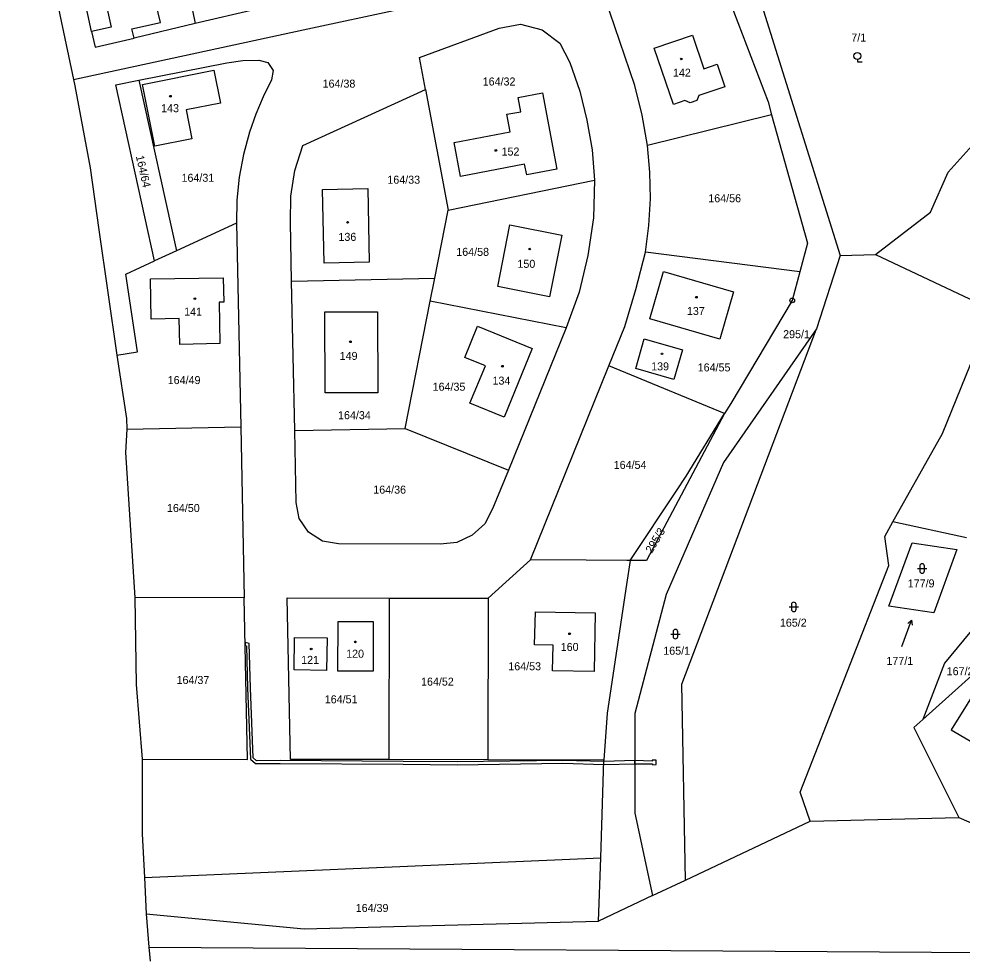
# Model space of a CAD drawing. Extents: x -779723 to -777378, y -1011169 to -1009297.
# Drawn here: x -779423.2 to -779222.9, y -1010475.7 to -1010276.4 of the extents above; entities that cross this region are included whole.
import ezdxf

# ---------------------------------------------------------------- set-up
doc = ezdxf.new("R2010")
doc.units = 0
for name, color, linetype in [('Hranice parcel', 7, 'Continuous'), ('Parcelní čísla', 7, 'Continuous'), ('Poz předměty', 7, 'Continuous'), ('Věcná břemena k části', 7, 'Continuous'), ('Značky bodu BP', 7, 'Continuous'), ('Značky budov', 7, 'Continuous'), ('Značky kultur', 7, 'Continuous')]:
    doc.layers.add(name, color=color, linetype=linetype)

msp = doc.modelspace()

# ---------------------------------------------------------------- linework, layer by layer
at = {"layer": 'Hranice parcel'}
for p, q in [((-779423.17, -1010234.28), (-779411.57, -1010289.24)), ((-779390.67, -1010252.85), (-779385.75, -1010277.38)), ((-779407.72, -1010279.08), (-779412.45, -1010257.73)), ((-779292.43, -1010290.53), (-779300.99, -1010265.39)), ((-779372.96, -1010274.36), (-779385.75, -1010277.38)), ((-779385.75, -1010277.38), (-779398.69, -1010280.44)), ((-779397.7, -1010289.41), (-779389.74, -1010325.58)), ((-779336.86, -1010291.37), (-779332.05, -1010316.98)), ((-779263.36, -1010296.74), (-779289.73, -1010303.24)), ((-779332.05, -1010316.98), (-779301, -1010310.57)), ((-779334.89, -1010331.42), (-779332.05, -1010316.98)), ((-779406.22, -1010321.12), (-779402.4, -1010347.73)), ((-779376.98, -1010319.73), (-779389.74, -1010325.58)), ((-779376.98, -1010319.73), (-779376.08, -1010362.91)), ((-779389.74, -1010325.58), (-779394.39, -1010327.71)), ((-779257.37, -1010330.02), (-779290.15, -1010325.87)), ((-779248.83, -1010326.61), (-779253.82, -1010342.15)), ((-779248.83, -1010326.61), (-779241.34, -1010326.4)), ((-779365.26, -1010332.05), (-779334.89, -1010331.42)), ((-779364.6, -1010363.75), (-779365.26, -1010332.05)), ((-779335.84, -1010336.25), (-779334.89, -1010331.42)), ((-779341.15, -1010363.28), (-779335.84, -1010336.25)), ((-779307.01, -1010341.91), (-779335.84, -1010336.25)), ((-779307.01, -1010341.91), (-779319.25, -1010372.13)), ((-779402.4, -1010347.73), (-779397.95, -1010347.05)), ((-779314.54, -1010391.18), (-779297.93, -1010350.03)), ((-779273.36, -1010360.11), (-779297.93, -1010350.03)), ((-779400.24, -1010363.41), (-779376.08, -1010362.91)), ((-779376.08, -1010362.91), (-779375.32, -1010399.25)), ((-779364.6, -1010363.75), (-779341.15, -1010363.28)), ((-779341.15, -1010363.28), (-779319.25, -1010372.13)), ((-779400.24, -1010363.41), (-779400.52, -1010368.39)), ((-779400.52, -1010368.39), (-779398.58, -1010399.19)), ((-779222.02, -1010386.49), (-779237.61, -1010383.13)), ((-779323.52, -1010399.33), (-779314.54, -1010391.18)), ((-779375.32, -1010399.25), (-779398.58, -1010399.19)), ((-779374.61, -1010433.5), (-779375.32, -1010399.25)), ((-779344.55, -1010433.56), (-779344.47, -1010399.29)), ((-779344.47, -1010399.29), (-779323.52, -1010399.33)), ((-779323.52, -1010399.33), (-779323.6, -1010433.61)), ((-779231.29, -1010425.07), (-779220.25, -1010415.13)), ((-779396.98, -1010433.44), (-779374.61, -1010433.5)), ((-779323.6, -1010433.61), (-779344.55, -1010433.56)), ((-779298.95, -1010433.67), (-779323.6, -1010433.61)), ((-779299.64, -1010454.37), (-779298.95, -1010433.67)), ((-779281.67, -1010459.12), (-779255.18, -1010446.63)), ((-779255.18, -1010446.63), (-779223.61, -1010445.86)), ((-779396.51, -1010458.6), (-779299.64, -1010454.37)), ((-779300.09, -1010467.81), (-779299.64, -1010454.37)), ((-779396.51, -1010458.6), (-779396.12, -1010466.31)), ((-779288.66, -1010462.42), (-779281.67, -1010459.12)), ((-779288.66, -1010462.42), (-779300.09, -1010467.81))]:
    msp.add_line(p, q, dxfattribs=at)
for points in [[(-779267.64, -1010229.61), (-779274.18, -1010236), (-779275.45, -1010241.64), (-779248.83, -1010326.61)], [(-779276.95, -1010260.2), (-779264.13, -1010293.98), (-779263.36, -1010296.74)], [(-779398.69, -1010280.44), (-779399.16, -1010278.51), (-779393.09, -1010277.12), (-779396.07, -1010264.73), (-779406.08, -1010266.98), (-779403.57, -1010278.12), (-779407.72, -1010279.08)], [(-779411.57, -1010289.24), (-779362.78, -1010278.71), (-779320.52, -1010269.6)], [(-779407.72, -1010279.08), (-779406.99, -1010282.4), (-779398.69, -1010280.44)], [(-779336.86, -1010291.37), (-779338.14, -1010284.55), (-779321.24, -1010278.36), (-779316.65, -1010277.51), (-779312.1, -1010278.67), (-779308.36, -1010281.51), (-779306.17, -1010285.63), (-779304.1, -1010291.71), (-779302.56, -1010297.89), (-779301.46, -1010304.17), (-779301, -1010310.57)], [(-779280.65, -1010294.17), (-779281.79, -1010293.68), (-779284.23, -1010294.51), (-779288.27, -1010282.58), (-779280.15, -1010279.85), (-779277.75, -1010286.96), (-779274.91, -1010286.01), (-779273.29, -1010290.79), (-779278.8, -1010292.6), (-779279.24, -1010293.68), (-779280.65, -1010294.17)], [(-779397.7, -1010289.41), (-779379.01, -1010285.72), (-779375.64, -1010285.2), (-779372.24, -1010285.16), (-779370.29, -1010285.62), (-779369.18, -1010287.35), (-779369.57, -1010289.31), (-779371.31, -1010292.92), (-779372.85, -1010296.61), (-779374.18, -1010300.38), (-779375.49, -1010305.12), (-779376.4, -1010309.95), (-779376.91, -1010314.83), (-779376.98, -1010319.73)], [(-779411.57, -1010289.24), (-779411.29, -1010290.56), (-779408.01, -1010308), (-779406.22, -1010321.12)], [(-779380.38, -1010294.23), (-779387.63, -1010295.67), (-779386.44, -1010301.84), (-779394.32, -1010303.41), (-779396.93, -1010290.27), (-779381.75, -1010287.29), (-779380.38, -1010294.23)], [(-779394.39, -1010327.71), (-779402.61, -1010290.38), (-779397.7, -1010289.41)], [(-779289.73, -1010303.24), (-779290.82, -1010296.83), (-779292.43, -1010290.53)], [(-779365.26, -1010332.05), (-779365.52, -1010319.51), (-779365.44, -1010313.99), (-779364.55, -1010308.53), (-779362.87, -1010303.27), (-779336.86, -1010291.37)], [(-779312.04, -1010292.07), (-779308.98, -1010308.25), (-779315.34, -1010309.48), (-779315.8, -1010307.17), (-779329.38, -1010309.79), (-779330.76, -1010302.6), (-779318.86, -1010300.34), (-779319.57, -1010296.61), (-779316.63, -1010296.07), (-779317.19, -1010293.07), (-779312.04, -1010292.07)], [(-779263.36, -1010296.74), (-779255.74, -1010323.95), (-779257.37, -1010330.02)], [(-779241.34, -1010326.4), (-779229.64, -1010317.38), (-779225.92, -1010308.91), (-779220.82, -1010303.25), (-779218.66, -1010301.14)], [(-779290.15, -1010325.87), (-779289.42, -1010320.24), (-779289.09, -1010314.57), (-779289.19, -1010308.89), (-779289.73, -1010303.24)], [(-779301, -1010310.57), (-779301.2, -1010318.61), (-779302.4, -1010326.55), (-779304.22, -1010334.38), (-779307.01, -1010341.91)], [(-779349.07, -1010312.38), (-779348.8, -1010328.01), (-779358.39, -1010328.18), (-779358.71, -1010312.55), (-779349.07, -1010312.38)], [(-779310.5, -1010335.33), (-779321.5, -1010333.19), (-779318.95, -1010320.1), (-779307.92, -1010322.25), (-779310.5, -1010335.33)], [(-779297.93, -1010350.03), (-779294.54, -1010341.64), (-779292.21, -1010333.83), (-779290.15, -1010325.87)], [(-779241.34, -1010326.4), (-779216.41, -1010338.1), (-779212.98, -1010339.7)], [(-779397.95, -1010347.05), (-779400.48, -1010330.51), (-779394.39, -1010327.71)], [(-779380.48, -1010345.29), (-779388.99, -1010345.45), (-779389.11, -1010339.96), (-779395.11, -1010340.07), (-779395.24, -1010331.56), (-779379.78, -1010331.29), (-779379.66, -1010336.48), (-779380.68, -1010336.5), (-779380.48, -1010345.29)], [(-779289.25, -1010340.01), (-779286.34, -1010329.98), (-779271.46, -1010334.31), (-779274.38, -1010344.34), (-779289.25, -1010340.01)], [(-779257.37, -1010330.02), (-779259, -1010336.11), (-779272.05, -1010357.97), (-779273.36, -1010360.11)], [(-779346.99, -1010355.72), (-779358.16, -1010355.75), (-779358.24, -1010338.57), (-779347.03, -1010338.54), (-779346.99, -1010355.72)], [(-779237.61, -1010383.13), (-779227.1, -1010364.33), (-779217.17, -1010339.95), (-779210.43, -1010343.11), (-779209.31, -1010341.42)], [(-779325.78, -1010341.59), (-779314.2, -1010346.31), (-779320.16, -1010360.9), (-779327.4, -1010357.94), (-779324.14, -1010349.97), (-779328.48, -1010348.2), (-779325.78, -1010341.59)], [(-779253.82, -1010342.15), (-779273.57, -1010370.48), (-779285.76, -1010398.5), (-779292.43, -1010423.76), (-779292.43, -1010444.9), (-779288.66, -1010462.42)], [(-779281.67, -1010459.12), (-779282.45, -1010417.52), (-779253.82, -1010342.15)], [(-779292.22, -1010350.54), (-779290.41, -1010344.29), (-779282.31, -1010346.63), (-779284.12, -1010352.88), (-779292.22, -1010350.54)], [(-779402.4, -1010347.73), (-779400.35, -1010361.15), (-779400.24, -1010363.41)], [(-779273.36, -1010360.11), (-779289.96, -1010391.32), (-779293.41, -1010391.29)], [(-779293.41, -1010391.29), (-779283.54, -1010376.5), (-779281.48, -1010373.4), (-779273.36, -1010360.11)], [(-779319.25, -1010372.13), (-779322.59, -1010380.37), (-779324.28, -1010383.52), (-779326.93, -1010385.93), (-779330.18, -1010387.47), (-779333.72, -1010387.84), (-779355.3, -1010387.79), (-779358.73, -1010387.21), (-779361.65, -1010385.29), (-779363.63, -1010382.4), (-779364.28, -1010378.98), (-779364.6, -1010363.75)], [(-779255.18, -1010446.63), (-779257.31, -1010440.46), (-779238.48, -1010392.35), (-779239.31, -1010386.18), (-779237.61, -1010383.13)], [(-779233.52, -1010387.55), (-779224.02, -1010388.94), (-779228.95, -1010402.41), (-779238.5, -1010401), (-779233.52, -1010387.55)], [(-779293.41, -1010391.29), (-779294.13, -1010391.29), (-779302.76, -1010391.24), (-779314.54, -1010391.18)], [(-779293.41, -1010391.29), (-779294.17, -1010396.39), (-779298.26, -1010423.68), (-779298.95, -1010433.67)], [(-779398.58, -1010399.19), (-779398.25, -1010417.61), (-779396.98, -1010433.44)], [(-779344.55, -1010433.56), (-779365.48, -1010433.52), (-779366.19, -1010399.24), (-779344.47, -1010399.29)], [(-779313.52, -1010402.22), (-779300.8, -1010402.42), (-779301.03, -1010414.86), (-779309.87, -1010414.71), (-779309.77, -1010409.3), (-779313.67, -1010409.23), (-779313.52, -1010402.22)], [(-779347.94, -1010404.25), (-779347.97, -1010414.8), (-779355.43, -1010414.78), (-779355.41, -1010404.25), (-779347.94, -1010404.25)], [(-779219.94, -1010404.96), (-779226.66, -1010413.11), (-779231.29, -1010425.07)], [(-779220.25, -1010415.13), (-779218.42, -1010416.38), (-779225.24, -1010427.24), (-779218.62, -1010431.11), (-779211.9, -1010420.85), (-779198.89, -1010413.78), (-779195.38, -1010405.25)], [(-779357.75, -1010407.71), (-779357.86, -1010414.64), (-779364.73, -1010414.54), (-779364.63, -1010407.66), (-779357.75, -1010407.71)], [(-779231.29, -1010425.07), (-779233.15, -1010426.74), (-779223.61, -1010445.86)], [(-779396.98, -1010433.44), (-779396.97, -1010449.31), (-779396.51, -1010458.6)], [(-779223.61, -1010445.86), (-779200.73, -1010455.74), (-779202.13, -1010460.62), (-779187.71, -1010466.11), (-779165.75, -1010470.45)], [(-779396.12, -1010466.31), (-779395.56, -1010473.38), (-779395.32, -1010476.34)], [(-779396.12, -1010466.31), (-779362.62, -1010469.45), (-779300.09, -1010467.81)]]:
    msp.add_lwpolyline(points, dxfattribs=at)
at = {"layer": 'Poz předměty'}
msp.add_line((-779395.56, -1010473.38), (-779130.44, -1010475.03), dxfattribs=at)
at = {"layer": 'Věcná břemena k části'}
for points in [[(-779375.12, -1010408.68), (-779375.11, -1010409.31), (-779374.83, -1010409.38), (-779374.61, -1010418.38), (-779373.99, -1010433.44), (-779372.95, -1010434.4), (-779367.73, -1010434.36), (-779341.57, -1010434.56), (-779330.15, -1010434.64), (-779307.72, -1010434.32), (-779298.98, -1010434.62), (-779292.43, -1010434.44), (-779292.43, -1010433.75), (-779298.96, -1010433.96), (-779307.72, -1010433.72), (-779330.15, -1010434.04), (-779341.57, -1010433.96), (-779367.73, -1010433.76), (-779372.71, -1010433.8), (-779373.41, -1010433.16), (-779374.01, -1010418.36), (-779374.25, -1010408.9)], [(-779292.43, -1010433.75), (-779292.43, -1010434.44), (-779288.68, -1010434.47), (-779288.68, -1010434.64), (-779287.86, -1010434.63), (-779287.87, -1010433.7), (-779288.69, -1010433.71), (-779288.69, -1010433.87)]]:
    msp.add_lwpolyline(points, close=True, dxfattribs=at)
at = {"layer": 'Značky bodu BP'}
for radius in [0.5, 0.0303]:
    msp.add_circle((-779259, -1010336.11), radius, dxfattribs=at)
at = {"layer": 'Značky budov'}
for centre in [(-779282.54, -1010284.87), (-779390.99, -1010292.78), (-779321.9, -1010304.29), (-779353.37, -1010319.55), (-779314.72, -1010325.22), (-779279.33, -1010335.44), (-779385.81, -1010335.73), (-779352.78, -1010344.9), (-779286.65, -1010347.45), (-779320.5, -1010350.07), (-779306.26, -1010406.86), (-779351.73, -1010408.58), (-779361.1, -1010410.08)]:
    msp.add_circle(centre, 0.175, dxfattribs=at)
at = {"layer": 'Značky kultur'}
for p, q in [((-779245.16, -1010284.99), (-779245.16, -1010285.49)), ((-779245.16, -1010285.49), (-779244.16, -1010285.49)), ((-779232.41, -1010393), (-779230.41, -1010393)), ((-779231.91, -1010392.5), (-779231.91, -1010393.5)), ((-779230.91, -1010393.5), (-779230.91, -1010392.5)), ((-779259.67, -1010401.15), (-779257.67, -1010401.15)), ((-779259.17, -1010400.65), (-779259.17, -1010401.65)), ((-779258.17, -1010401.65), (-779258.17, -1010400.65)), ((-779235.71, -1010409.58), (-779233.66, -1010403.94)), ((-779233.66, -1010403.94), (-779234.46, -1010404.68)), ((-779233.66, -1010403.94), (-779233.52, -1010405.03)), ((-779284.79, -1010406.92), (-779282.79, -1010406.92)), ((-779284.29, -1010406.42), (-779284.29, -1010407.42)), ((-779283.29, -1010407.42), (-779283.29, -1010406.42))]:
    msp.add_line(p, q, dxfattribs=at)
msp.add_circle((-779245.16, -1010284.24), 0.75, dxfattribs=at)
for centre, start, end in [((-779231.41, -1010392.5), 0, 180), ((-779231.41, -1010393.5), 180, 359.9879), ((-779258.67, -1010400.65), 0, 180), ((-779258.67, -1010401.65), 180, 359.9879), ((-779283.79, -1010406.42), 0, 180), ((-779283.79, -1010407.42), 180, 359.9879)]:
    msp.add_arc(centre, 0.5, start, end, dxfattribs=at)

# ---------------------------------------------------------------- texts
at = {"layer": 'Parcelní čísla'}
for s, p in [('7/1', (-779246.45, -1010281.18)), ('142', (-779284.31, -1010288.64)), ('164/38', (-779358.69, -1010290.96)), ('164/32', (-779324.7, -1010290.51)), ('143', (-779392.97, -1010296.17)), ('152', (-779320.7, -1010305.38)), ('164/31', (-779388.64, -1010310.94)), ('164/33', (-779344.94, -1010311.35)), ('164/56', (-779276.81, -1010315.29)), ('136', (-779355.33, -1010323.48)), ('164/58', (-779330.31, -1010326.66)), ('150', (-779317.33, -1010329.2)), ('141', (-779388.08, -1010339.35)), ('137', (-779281.35, -1010339.21)), ('295/1', (-779260.92, -1010344.13)), ('149', (-779355.07, -1010348.74)), ('139', (-779288.94, -1010350.96)), ('164/55', (-779279.06, -1010351.18)), ('164/49', (-779391.57, -1010353.87)), ('134', (-779322.62, -1010353.98)), ('164/35', (-779335.33, -1010355.28)), ('164/34', (-779355.41, -1010361.32)), ('164/54', (-779296.89, -1010371.87)), ('164/36', (-779347.93, -1010377.12)), ('164/50', (-779391.73, -1010381.02)), ('177/9', (-779234.47, -1010397.01)), ('165/2', (-779261.61, -1010405.35)), ('160', (-779308.14, -1010410.5)), ('120', (-779353.69, -1010411.94)), ('165/1', (-779286.37, -1010411.3)), ('121', (-779363.24, -1010413.25)), ('164/53', (-779319.27, -1010414.6)), ('177/1', (-779238.99, -1010413.45)), ('167/2', (-779226.2, -1010415.65)), ('164/37', (-779389.69, -1010417.51)), ('164/52', (-779337.79, -1010417.86)), ('164/51', (-779358.23, -1010421.61)), ('164/39', (-779351.66, -1010465.89))]:
    msp.add_text(s, height=1.7, dxfattribs=at).set_placement(p)
for s, rotation, p in [('164/64', 283, (-779398.35, -1010305.53)), ('295/3', 59, (-779288.81, -1010389.91))]:
    msp.add_text(s, height=1.7, rotation=rotation, dxfattribs=at).set_placement(p)

doc.saveas('drawing.dxf')
